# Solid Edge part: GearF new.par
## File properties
Author: vinurabandara
Template: iso metric part.par
Last saved by: Nimesh.N
Revision: 30
Application: Solid Edge
Density: 7250.000 kg/m^3
Accuracy: 0.990
Username: Nimesh.N
Material: Iron:0.6025 , EN-GJL-250
Face Style: Gray
Fill Style: ANSI31(Iron)
Grouping: Iron\Gray Cast Iron
LibraryName: Materials-DIN
Coef. of Thermal Exp: 1.05e-05
Thermal Conductivity: 58.0
Specific Heat: 460.0
Modulus of Elasticity: 120000003072.0
Poisson's Ratio: 0.26
Yield Stress: 165593984.0
Ultimate Stress: 250000000.0
Elongation: 0.0
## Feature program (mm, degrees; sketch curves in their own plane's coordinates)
sketch for "unnamed Protrusion 1" plane through (0, 0, 0) normal (0, 0, 1) x-axis (1, 0, 0)
  circle centre (0, 0) radius 245
extrude "unnamed Protrusion 1" add finite 130 along -normal
sketch used by "unnamed Cutout 1" plane through (0, 0, 0) normal (0, 0, 1) x-axis (1, 0, 0)
  line (0, 0) -> (-16.3642, 244.4529)
  line (0, 0) -> (-13.6399, 244.62)
  line (0, 0) -> (-42.5438, 241.2779)
  line (-3.7179, 222.4689) -> (3.7179, 222.4689)
  arc centre (-62.3049, 209.5241) radius 60 from (-13.6399, 244.62) to (-3.7179, 222.4689) cw
  arc centre (62.3049, 209.5241) radius 60 from (13.6399, 244.62) to (3.7179, 222.4689) ccw
extrude "unnamed Cutout 1" cut through along -normal
pattern "unnamed Pattern 1" of "unnamed Cutout 1"
pattern "unnamed Pattern 2"
sketch for "unnamed Cutout 2" plane through (0, 0, 0) normal (0, 0, 1) x-axis (-0.166329, 0.98607, 0)
extrude "unnamed Cutout 2" cut through along -normal
sketch for "unnamed Cutout 3" plane through (0, 0, 0) normal (0, 0, 1) x-axis (-0.166329, 0.98607, 0)
  line (-8.125, 39.8042) -> (-8.125, 31.468)
  line (8.125, 39.8042) -> (8.125, 31.468)
extrude "unnamed Cutout 3" cut through along -normal
pattern "unnamed Pattern 3" of "unnamed Cutout 3"
pattern "unnamed Pattern 4"
sketch used by "unnamed Protrusion 2" plane through (0, 0, 0) normal (0, 0, 1) x-axis (1, 0, 0)
  circle centre (0, 0) radius 245
extrude "unnamed Protrusion 2" add finite
sketch for "unnamed Protrusion 3" #1 plane through (0, 0, 0) normal (0, 0, 1) x-axis (-0.166329, 0.98607, 0)
sketch for "unnamed Protrusion 3" #2 plane through (0, 0, 0) normal (0, 0, 1) x-axis (-0.166329, 0.98607, 0)
extrude "unnamed Protrusion 3" add finite
sketch for "unnamed Protrusion 4" plane through (0, 0, 0) normal (0, 0, 1) x-axis (-0.166329, 0.98607, 0)
extrude "unnamed Protrusion 4" add finite
sketch for "unnamed Protrusion 5" plane through (0, 0, 0) normal (0, 0, 1) x-axis (-0.166329, 0.98607, 0)
  circle centre (0, 0) radius 150.1838
extrude "unnamed Protrusion 5" add finite
sketch for "unnamed Protrusion 6" plane through (0, 0, 0) normal (0, 0, 1) x-axis (-0.166329, 0.98607, 0)
  circle centre (0, 0) radius 135.167
extrude "unnamed Protrusion 6" add finite
sketch for "unnamed Cutout 4" #1 plane through (0, 0, 0) normal (0, 0, 1) x-axis (-0.166329, 0.98607, 0)
  circle centre (0, 0) radius 89
sketch for "unnamed Cutout 4" #2 plane through (0, 0, 0) normal (0, 0, 1) x-axis (-0.166329, 0.98607, 0)
  circle centre (0, 0) radius 200.25
extrude "unnamed Cutout 4" cut finite 35 along -normal
mirror "unnamed Mirror 1" of "unnamed Cutout 4"
pattern "unnamed Pattern 5"
sketch for "unnamed Cutout 5" plane through (0, 0, -35) normal (0, 0, 1) x-axis (1, 0, 0)
extrude "unnamed Cutout 5" cut through along -normal
pattern "unnamed Pattern 6" of "unnamed Cutout 5"
pattern "unnamed Pattern 7"
fillet "unnamed Round 1"
fillet "Round_3" radius 10
sketch for "ExtrudedProtrusion_9" #1 plane through (0, 0, -130) normal (0, 0, -1) x-axis (0, 1, 0)
sketch for "ExtrudedProtrusion_9" #2 plane through (0, 0, -130) normal (0, 0, -1) x-axis (0, 1, 0)
  arc centre (0, 0) radius 32.5 from (29.6782, -13.2459) to (24.8611, -20.9327) cw
  line (29.6931, -27.7256) -> (24.8611, -20.9327)
  arc centre (0, 0) radius 40.625 from (16.4515, -37.1448) to (29.6931, -27.7256) ccw
  line (11.6194, -30.3519) -> (16.4515, -37.1448)
  arc centre (0, 0) radius 32.5 from (11.6194, -30.3519) to (2.7778, -32.3811) cw
  line (1.3912, -40.6012) -> (2.7778, -32.3811)
  arc centre (0, 0) radius 40.625 from (-14.6324, -37.8983) to (1.3912, -40.6012) ccw
  line (-13.2459, -29.6782) -> (-14.6324, -37.8983)
  arc centre (0, 0) radius 32.5 from (-13.2459, -29.6782) to (-20.9327, -24.8611) cw
extrude "ExtrudedProtrusion_9" add finite 15 along +normal
sketch for "unnamed Protrusion 7" #1 plane through (0, 0, -145) normal (0, 0, -1) x-axis (1, 0, 0)
sketch for "unnamed Protrusion 7" #2 plane through (0, 0, -145) normal (0, 0, -1) x-axis (1, 0, 0)
  circle centre (0, 0) radius 104
extrude "unnamed Protrusion 7" add finite 5 along -normal
Other named dimensions: "ExtrudedSurface_3": FiniteDepth = 130 mm
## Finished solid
Body 1: sheet body, 1 face, 2 edges, 0 vertices.
  Faces by surface: cylinder 1
  Edges by curve: circle 2
Body 2: solid body, 264 faces, 766 edges, 504 vertices.
  Faces by surface: cylinder 186, plane 78
  Edges by curve: line 394, circle 372
Bounding box of the edges (mm): 489.878 x 489.620 x 145.000, from (-244.9392, -245, -145) to (244.9392, 244.62, 0).
Cylindrical faces by radius (mm): R10 x16, R32.5 x8, R40.625 x8, R60 x94, R89 x2, R104 x1, R106.8 x4, R184.675 x4, R200.25 x2, R235 x1, R245 x47
Planar faces by outward normal: +y 1, +z 4, -z 3, oblique 70
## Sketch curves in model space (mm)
line (0, 0, 0) -> (-42.5438, 241.2779, 0)
line (0, 0, 0) -> (-16.3642, 244.4529, 0)
line (0, 0, 0) -> (4.0939, 244.9658, 0)
line (0, 0, 0) -> (-4.0939, 244.9658, 0)
arc centre (62.3049, 209.5241, 0) radius 60 from (13.6399, 244.62, 0) through (7.5471, 234.0514, 0) to (3.7179, 222.4689, 0)
line (-3.7179, 222.4689, 0) -> (3.7179, 222.4689, 0)
arc centre (-62.3049, 209.5241, 0) radius 60 from (-13.6399, 244.62, 0) through (-7.5471, 234.0514, 0) to (-3.7179, 222.4689, 0)
line (0, 0, 0) -> (-13.6399, 244.62, 0)
circle centre (0, 0, 0) radius 245
circle centre (0, 0, 0) radius 235
circle centre (0, 0, 0) radius 222.5
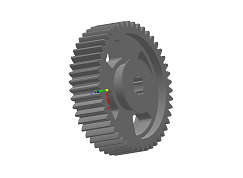
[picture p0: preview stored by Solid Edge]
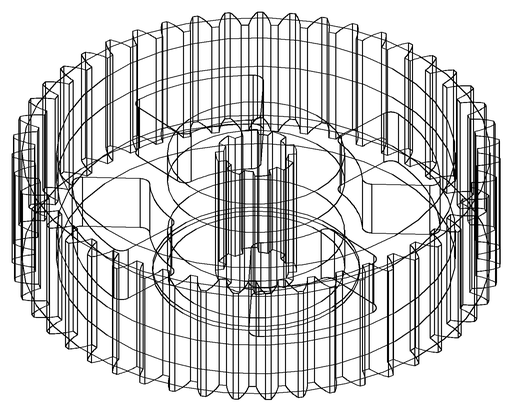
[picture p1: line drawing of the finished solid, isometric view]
